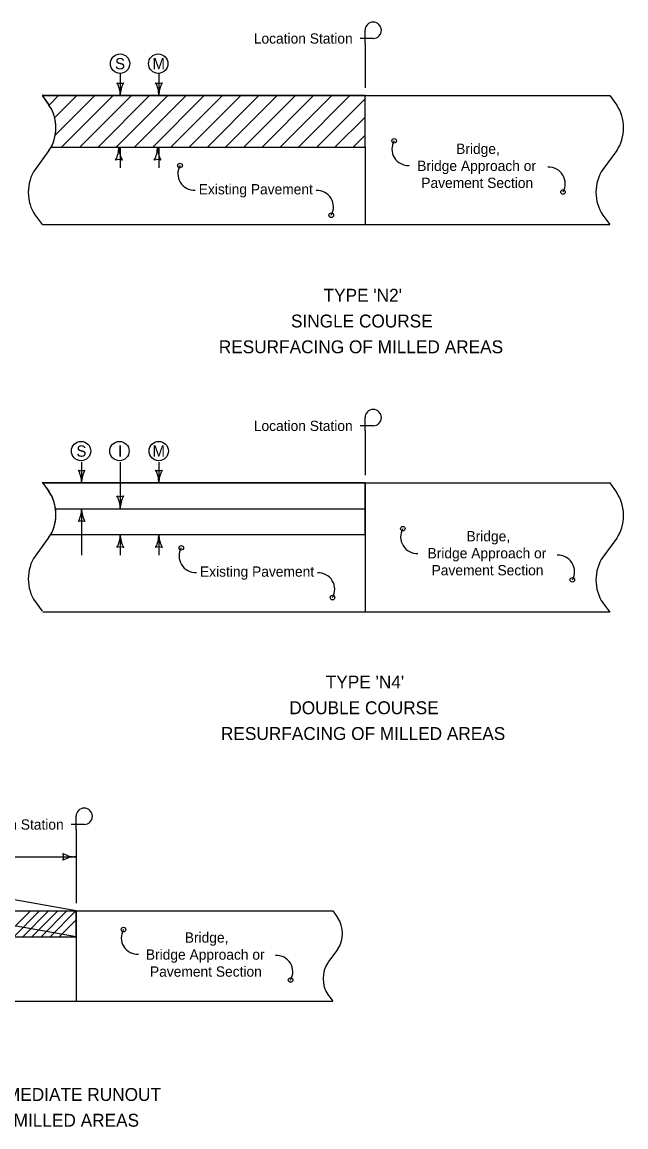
# Model space of a CAD drawing. Extents: x 10133 to 81668, y 2218 to 11018.
# Drawn here: x 15959 to 16897, y 2218 to 3932 of the extents above; entities that cross this region are included whole.
import ezdxf

# ---------------------------------------------------------------- set-up
doc = ezdxf.new("R2010")
doc.units = 0
for name, color, linetype in [('dsnCellElements', 7, 'Continuous'), ('dsnNonPlotable', 7, 'Continuous'), ('dsnStdBlock', 7, 'Continuous'), ('dsnstdblockInterim', 7, 'Continuous'), ('dsnStdBlockNotModified', 7, 'Continuous'), ('dsnStgShadingPropPav', 7, 'Continuous'), ('Level 7', 7, 'Continuous')]:
    doc.layers.add(name, color=color, linetype=linetype)

msp = doc.modelspace()

# ---------------------------------------------------------------- linework, layer by layer
at = {"layer": 'dsnCellElements'}
for p, q in [((16001, 3803.6), (16015.7, 3818.3)), ((16009.8, 3784.1), (16044, 3818.3)), ((16010.7, 3756.7), (16072.3, 3818.3)), ((16020.5, 3738.3), (16100.5, 3818.3)), ((16048.8, 3738.3), (16128.8, 3818.3)), ((16077.1, 3738.3), (16157.1, 3818.3)), ((16105.4, 3738.3), (16185.4, 3818.3)), ((16133.7, 3738.3), (16213.7, 3818.3)), ((16162, 3738.3), (16242, 3818.3)), ((16190.3, 3738.3), (16270.3, 3818.3)), ((16218.5, 3738.3), (16298.5, 3818.3)), ((16246.8, 3738.3), (16326.8, 3818.3)), ((16275.1, 3738.3), (16355.1, 3818.3)), ((16303.4, 3738.3), (16383.4, 3818.3)), ((16331.7, 3738.3), (16411.7, 3818.3)), ((16360, 3738.3), (16440, 3818.3)), ((16388.2, 3738.3), (16468.2, 3818.3)), ((16416.5, 3738.3), (16491.5, 3813.3)), ((16444.8, 3738.3), (16491.5, 3785)), ((16473.1, 3738.3), (16491.5, 3756.7))]:
    msp.add_line(p, q, dxfattribs=at)
at = {"layer": 'dsnNonPlotable'}
for p, q in [((16491.5, 3217.3), (15991.1, 3217.3)), ((15991.1, 3217.3), (16001, 3203.9)), ((16491.5, 3217.3), (15991.1, 3217.3)), ((15991.1, 3217.3), (16001, 3203.9)), ((16491.5, 3137.3), (16491.5, 3217.3)), ((16491.5, 3137.3), (16491.5, 3217.3)), ((16003.6, 3137.3), (16491.5, 3137.3)), ((16003.6, 3137.3), (16491.5, 3137.3)), ((16042.9, 2553.2), (15705.4, 2613.2)), ((16042.9, 2513.2), (16042.9, 2553.2)), ((15342.4, 2513.2), (16042.9, 2513.2))]:
    msp.add_line(p, q, dxfattribs=at)
msp.add_ellipse((15975, 3168.5), major_axis=(0, -50), ratio=0.732645, start_param=0.89539, end_param=2.356194, dxfattribs=at)
msp.add_ellipse((15975, 3168.5), major_axis=(0, -50), ratio=0.732645, start_param=0.89539, end_param=2.356194, dxfattribs=at)
at = {"layer": 'dsnStdBlock'}
for p, q in [((16491.5, 3899.3), (16491.5, 3919.6)), ((16504.2, 3906.9), (16483.9, 3906.9)), ((16491.5, 3899.3), (16491.5, 3830.3)), ((16111.5, 3852.8), (16111.5, 3818.3)), ((16171.5, 3852.8), (16171.5, 3818.3)), ((15990.2, 3818.3), (16491.5, 3818.3)), ((15990.2, 3818.3), (16000.9, 3803.6)), ((16491.5, 3818.3), (16871.5, 3818.3)), ((16491.5, 3738.3), (16491.5, 3818.3)), ((16871.5, 3818.3), (16882.2, 3803.6)), ((16004.4, 3738.3), (16491.5, 3738.3)), ((16111.5, 3738.3), (16111.5, 3706.3)), ((16171.5, 3738.3), (16171.5, 3706.3)), ((16491.5, 3738.3), (16491.5, 3618.3)), ((16000.9, 3732.9), (15979.5, 3703.6)), ((16882.2, 3732.9), (16860.8, 3703.6)), ((15979.5, 3632.9), (15990.2, 3618.3)), ((15991.1, 3618.3), (16871.5, 3618.3)), ((16860.8, 3632.9), (16871.5, 3618.3)), ((16491.5, 3298.3), (16491.5, 3318.6)), ((16504.2, 3305.9), (16483.9, 3305.9)), ((16491.5, 3298.3), (16491.5, 3229.3)), ((16051.5, 3249.3), (16051.5, 3217.3)), ((16111.5, 3249.3), (16111.5, 3177.3)), ((16171.5, 3249.3), (16171.5, 3217.3)), ((15990.2, 3218.5), (16000.9, 3203.9)), ((15991.5, 3217.3), (16491.5, 3217.3)), ((16491.5, 3217.3), (16491.5, 3137.3)), ((16491.5, 3217.3), (16871.5, 3217.3)), ((16871.5, 3217.3), (16882.2, 3202.1)), ((16011.1, 3177.3), (16491.5, 3177.3)), ((16051.5, 3177.3), (16051.5, 3105.3)), ((16003.9, 3137.3), (16491.5, 3137.3)), ((16111.5, 3137.3), (16111.5, 3105.3)), ((16171.5, 3137.3), (16171.5, 3105.3)), ((16491.2, 3137.3), (16491.5, 3137.6)), ((16491.5, 3137.3), (16491.5, 3017.3)), ((16000.9, 3133.2), (15979.5, 3103.9)), ((16882.2, 3131.4), (16860.8, 3102.1)), ((15979.5, 3033.2), (15990.2, 3018.5)), ((15991.5, 3017.3), (16871.5, 3017.3)), ((16860.8, 3031.4), (16871.5, 3016.7)), ((16042.9, 2679.8), (16042.9, 2700.1)), ((16055.6, 2687.4), (16035.3, 2687.4)), ((16042.9, 2679.8), (16042.9, 2565.2)), ((15891.7, 2637.2), (16042.9, 2637.2)), ((16042.9, 2553.2), (15705.4, 2613.2)), ((16042.9, 2513.2), (15705.4, 2573.2)), ((15817.9, 2553.2), (16042.9, 2553.2)), ((15932.1, 2513.2), (15972.1, 2553.2)), ((15946.2, 2513.2), (15986.2, 2553.2)), ((15960.4, 2513.2), (16000.4, 2553.2)), ((15974.5, 2513.2), (16014.5, 2553.2)), ((15988.7, 2513.2), (16028.7, 2553.2)), ((16002.8, 2513.2), (16042.8, 2553.2)), ((16016.9, 2513.2), (16042.9, 2539.2)), ((16042.9, 2553.2), (16042.9, 2413.2)), ((16042.9, 2553.2), (16441.4, 2553.2)), ((16441.4, 2553.2), (16448.9, 2543)), ((15342.4, 2513.2), (16042.9, 2513.2)), ((16448.9, 2493.5), (16433.9, 2473)), ((16433.9, 2423.5), (16441.4, 2413.2)), ((15344.3, 2413.2), (16441.4, 2413.2))]:
    msp.add_line(p, q, dxfattribs=at)
for centre, radius in [((16111.3, 3867.8), 15), ((16170.5, 3867.8), 15), ((16050.7, 3266.8), 15), ((16110.3, 3266.8), 15), ((16171.3, 3266.8), 15), ((16116.6, 2524.3), 3.56), ((16376, 2446.1), 3.56)]:
    msp.add_circle(centre, radius, dxfattribs=at)
for centre, radius, start, end in [((16504.2, 3919.6), 12.7, 270, 180), ((16558.9, 3735.3), 25.6, 150.0683, 272.8436), ((16226.6, 3697.1), 25.6, 150.0683, 272.8436), ((16776.8, 3681.5), 25.6, 330.0683, 92.8436), ((16417, 3645.4), 25.6, 330.0683, 92.8436), ((16504.2, 3318.6), 12.7, 270, 180), ((16572.4, 3133.5), 25.6, 150.0683, 272.8436), ((16228.5, 3103.9), 25.6, 150.0683, 272.8436), ((16791.2, 3079.7), 25.6, 330.0683, 92.8436), ((16418.9, 3052.2), 25.6, 330.0683, 92.8436), ((16055.6, 2700.1), 12.7, 270, 180), ((16006.7, 2637.2), 16.7, 342.2666, 17.7333), ((16042.9, 2680.4), 43.2, 241.9275, 270), ((16042.9, 2594), 43.2, 90, 118.0725), ((16138.7, 2511.5), 25.6, 150.0683, 272.8436), ((16353.8, 2458.8), 25.6, 330.0683, 92.8436)]:
    msp.add_arc(centre, radius, start, end, dxfattribs=at)
for centre, major_axis, ratio in [((15975, 3768.3), (0, -50), 0.732645), ((16856.3, 3768.3), (0, -50), 0.732645), ((16005.4, 3668.3), (0, 50), 0.732645), ((16886.7, 3668.3), (0, 50), 0.732645), ((15975, 3168.5), (0, -50), 0.732645), ((16856.3, 3166.7), (0, -50), 0.732645), ((16005.4, 3068.5), (0, 50), 0.732645), ((16886.7, 3066.7), (0, 50), 0.732645), ((16430.8, 2518.2), (0, -35), 0.732627), ((16452, 2448.2), (0, 35), 0.732627)]:
    msp.add_ellipse(centre, major_axis=major_axis, ratio=ratio, start_param=0.785398, end_param=2.356194, dxfattribs=at)
at = {"layer": 'dsnstdblockInterim'}
for p, q in [((16491.5, 3818.3), (15990.2, 3818.3)), ((15990.2, 3818.3), (16001, 3803.6)), ((16491.5, 3738.3), (16491.5, 3818.3)), ((16004.4, 3738.3), (16491.5, 3738.3))]:
    msp.add_line(p, q, dxfattribs=at)
msp.add_ellipse((15975, 3768.3), major_axis=(0, -50), ratio=0.732645, start_param=0.927277, end_param=2.356194, dxfattribs=at)
at = {"layer": 'dsnStgShadingPropPav'}
for centre, radius, start, end in [((16111.5, 3853.9), 16.4, 252.2666, 287.7333), ((16069, 3818.3), 42.5, 360, 28.0725), ((16154, 3818.3), 42.5, 151.9275, 180), ((16171.5, 3853.9), 16.4, 252.2666, 287.7333), ((16129, 3818.3), 42.5, 360, 28.0725), ((16214, 3818.3), 42.5, 151.9275, 180), ((16066.9, 3738.3), 42.5, 331.9275, 360), ((16151.9, 3738.3), 42.5, 180, 208.0725), ((16126.9, 3738.3), 42.5, 331.9275, 360), ((16211.9, 3738.3), 42.5, 180, 208.0725), ((16109.4, 3702.6), 16.4, 72.2666, 107.7334), ((16169.4, 3702.6), 16.4, 72.2666, 107.7334), ((16051.5, 3252.9), 16.4, 252.2666, 287.7333), ((16009, 3217.3), 42.5, 360, 28.0725), ((16094, 3217.3), 42.5, 151.9275, 180), ((16171.5, 3252.9), 16.4, 252.2666, 287.7333), ((16129, 3217.3), 42.5, 360, 28.0725), ((16214, 3217.3), 42.5, 151.9275, 180), ((16111.5, 3212.9), 16.4, 252.2666, 287.7333), ((16069, 3177.3), 42.5, 360, 28.0725), ((16154, 3177.3), 42.5, 151.9275, 180), ((16009, 3177.3), 42.5, 331.9275, 360), ((16094, 3177.3), 42.5, 180, 208.0725), ((16051.5, 3141.6), 16.4, 72.2666, 107.7334), ((16069, 3137.3), 42.5, 331.9275, 360), ((16154, 3137.3), 42.5, 180, 208.0725), ((16129, 3137.3), 42.5, 331.9275, 360), ((16214, 3137.3), 42.5, 180, 208.0725), ((16111.5, 3101.6), 16.4, 72.2666, 107.7334), ((16171.5, 3101.6), 16.4, 72.2666, 107.7334)]:
    msp.add_arc(centre, radius, start, end, dxfattribs=at)
at = {"layer": 'Level 7'}
for centre in [(16536.7, 3748), (16204.4, 3709.9), (16798.9, 3668.7), (16439.1, 3632.6), (16550.3, 3146.3), (16550.3, 3146.3), (16206.4, 3116.7), (16813.4, 3066.9), (16441.1, 3039.4)]:
    msp.add_circle(centre, 3.54, dxfattribs=at)

# ---------------------------------------------------------------- texts
at = {"layer": 'dsnStdBlock'}
for s, p in [('S', (16103.4, 3859)), ('M', (16161.6, 3859))]:
    msp.add_text(s, height=17.5, dxfattribs=at).set_placement(p)
at = {"layer": 'dsnStdBlockNotModified'}
for s, height, p in [('Location Station', 16, (16318.9, 3898.9)), ('Bridge,', 16, (16633, 3727.7)), ('Bridge Approach or', 16, (16572.6, 3701.3)), ('Pavement Section', 16, (16578.9, 3674.9)), ('Existing Pavement', 16, (16233.4, 3665)), ("TYPE 'N2' ", 20, (16427.2, 3498.5)), ('SINGLE COURSE', 20, (16376.6, 3458.5)), ('RESURFACING OF MILLED AREAS', 20, (16264.5, 3418.5)), ('Location Station', 16, (16318.9, 3297.9)), ('S', 17.5, (16043.4, 3258)), ('I', 17.5, (16108.2, 3258)), ('M', 17.5, (16161.6, 3258)), ('Bridge,', 16, (16649, 3126.7)), ('Bridge Approach or', 16, (16588.6, 3100.3)), ('Existing Pavement', 16, (16235.3, 3071.8)), ('Pavement Section', 16, (16594.9, 3073.9)), ("TYPE 'N4'", 20, (16430.6, 2898.5)), ('DOUBLE COURSE', 20, (16374, 2858.5)), ('RESURFACING OF MILLED AREAS', 20, (16267.9, 2818.5)), ('Location Station', 16, (15870.3, 2679.4)), ('Bridge,', 16, (16211.7, 2504)), ('Bridge Approach or', 16, (16151.3, 2477.6)), ('Pavement Section', 16, (16157.7, 2451.2)), ('SURFACE NOTCH - INTERMEDIATE RUNOUT', 20, (15599.8, 2258.5)), ('FOR RESURFACING OF MILLED AREAS', 20, (15635.5, 2218.5))]:
    msp.add_text(s, height=height, dxfattribs=at).set_placement(p)

doc.saveas('drawing.dxf')
